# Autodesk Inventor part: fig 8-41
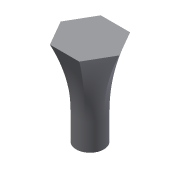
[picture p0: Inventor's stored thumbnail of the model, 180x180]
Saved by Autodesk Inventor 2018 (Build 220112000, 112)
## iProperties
Created: 2004-05
Part Number: fig 8-41
Document SubType Name: Modeling
Designer: CADCIM Technologies
Manufacturer: Standard
Standards Organization: Custom
Density: 1 g/cm^3
Material: Generic
Appearance: Default
Author: CADCIM Technologies
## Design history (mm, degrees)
sketch "Sketch1"
  geometry: C1 r 16.344 at (0, 0)
  constraints: 1 centre point
extrude "Extrusion1" new body sketch "Sketch1" distance "d0" = 30.75; taper "d1" = 0 deg
workplane "Work Plane1"
sketch "Sketch2"
  geometry: L1 (34.788, 0)-(17.394, -30.128); L2 (17.394, -30.128)-(-17.394, -30.128); L3 (-17.394, -30.128)-(-34.788, 0); L4 (-34.788, 0)-(-17.394, 30.128); L5 (-17.394, 30.128)-(17.394, 30.128); L6 (17.394, 30.128)-(34.788, 0); 2 further points
  constraints: 12 end point, 1 coincident, 12 other
loft "Loft2" sketch "Sketch2" dims "d8" = 90 deg, "d9" = 0, "d10" = 90 deg, "d11" = 10
  node "Edges2"
body "Solid1"
other parameters: "d2" = 75
